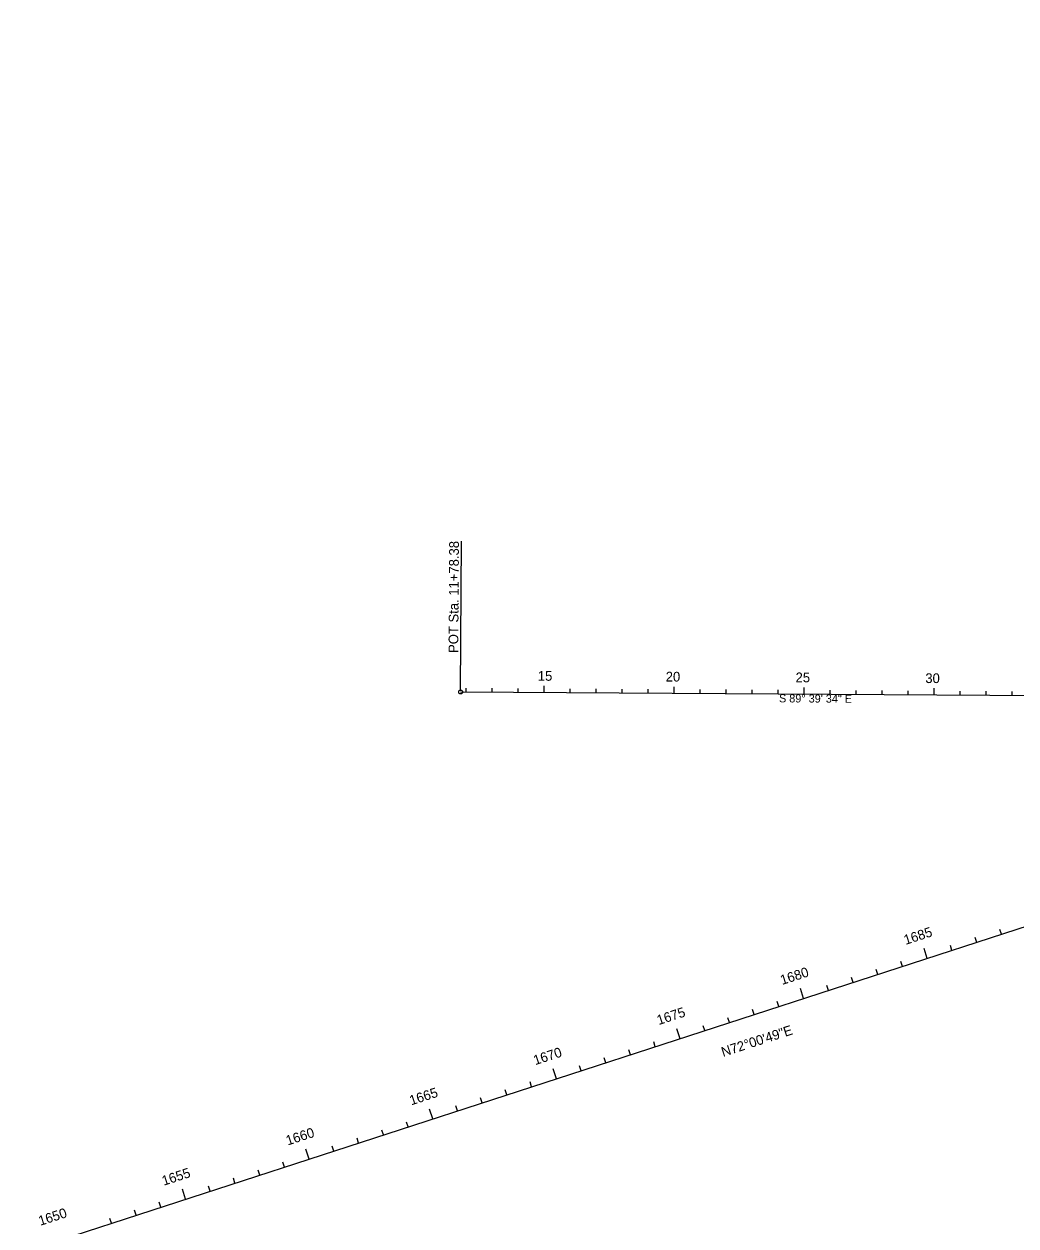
# Model space of a CAD drawing. Extents: x 1280727 to 1452510, y 526233 to 601451.
# Drawn here: x 1420802 to 1424618, y 582241 to 586865 of the extents above; entities that cross this region are included whole.
import ezdxf

# ---------------------------------------------------------------- set-up
doc = ezdxf.new("R2010")
doc.units = 0
for name, color, linetype in [('RW_X_CL', 7, 'Continuous'), ('RW_X_CL_500_Stations', 7, 'Continuous'), ('SH_Text', 7, 'Continuous')]:
    doc.layers.add(name, color=color, linetype=linetype)

msp = doc.modelspace()

# ---------------------------------------------------------------- linework, layer by layer
at = {"layer": 'RW_X_CL'}
for p, q in [((1406994.9, 577659.9), (1435349.1, 586865.3)), ((1422481.4, 584295.6), (1425214.5, 584279.4))]:
    msp.add_line(p, q, dxfattribs=at)
at = {"layer": 'RW_X_CL_500_Stations'}
for p, q in [((1422503, 584295.5), (1422503.1, 584310.5)), ((1422603, 584294.9), (1422603.1, 584309.9)), ((1422703, 584294.3), (1422703.1, 584309.3)), ((1422803, 584293.7), (1422803.1, 584318.7)), ((1422903, 584293.1), (1422903.1, 584308.1)), ((1423003, 584292.5), (1423003.1, 584307.5)), ((1423103, 584291.9), (1423103.1, 584306.9)), ((1423203, 584291.3), (1423203.1, 584306.3)), ((1423303, 584290.7), (1423303.1, 584315.7)), ((1423403, 584290.1), (1423403.1, 584305.1)), ((1423503, 584289.6), (1423503.1, 584304.6)), ((1423603, 584289), (1423603.1, 584304)), ((1423703, 584288.4), (1423703.1, 584303.4)), ((1423803, 584287.8), (1423803.1, 584312.8)), ((1424303, 584284.8), (1424303.1, 584309.8)), ((1423903, 584287.2), (1423903.1, 584302.2)), ((1424003, 584286.6), (1424003.1, 584301.6)), ((1424103, 584286), (1424103.1, 584301)), ((1424203, 584285.4), (1424203.1, 584300.4)), ((1424403, 584284.2), (1424403.1, 584299.2)), ((1424503, 584283.6), (1424503.1, 584298.6)), ((1424603, 584283), (1424603, 584298)), ((1424561.9, 583363.2), (1424555.7, 583382.2)), ((1424466.8, 583332.3), (1424460.6, 583351.3)), ((1424276.5, 583270.5), (1424264.2, 583308.6)), ((1424371.7, 583301.4), (1424365.5, 583320.4)), ((1424181.4, 583239.7), (1424175.2, 583258.7)), ((1423991.2, 583177.9), (1423985, 583196.9)), ((1424086.3, 583208.8), (1424080.1, 583227.8)), ((1423801, 583116.1), (1423788.6, 583154.2)), ((1423896.1, 583147), (1423889.9, 583166)), ((1423705.9, 583085.3), (1423699.7, 583104.3)), ((1423610.7, 583054.4), (1423604.6, 583073.4)), ((1423420.5, 582992.6), (1423414.3, 583011.6)), ((1423515.6, 583023.5), (1423509.5, 583042.5)), ((1423325.4, 582961.7), (1423313.1, 582999.8)), ((1423135.2, 582900), (1423129, 582919)), ((1423230.3, 582930.9), (1423224.1, 582949.9)), ((1423040.1, 582869.1), (1423033.9, 582888.1)), ((1422849.8, 582807.3), (1422837.5, 582845.4)), ((1422945, 582838.2), (1422938.8, 582857.2)), ((1422754.7, 582776.5), (1422748.6, 582795.5)), ((1422564.5, 582714.7), (1422558.3, 582733.7)), ((1422659.6, 582745.6), (1422653.4, 582764.6)), ((1422374.3, 582653), (1422361.9, 582691)), ((1422469.4, 582683.8), (1422463.2, 582702.9)), ((1422279.2, 582622.1), (1422273, 582641.1)), ((1422184.1, 582591.2), (1422177.9, 582610.2)), ((1421993.8, 582529.4), (1421987.6, 582548.5)), ((1422088.9, 582560.3), (1422082.8, 582579.3)), ((1421898.7, 582498.6), (1421886.4, 582536.6)), ((1421708.5, 582436.8), (1421702.3, 582455.8)), ((1421803.6, 582467.7), (1421797.4, 582486.7)), ((1421613.4, 582405.9), (1421607.2, 582424.9)), ((1421423.1, 582344.2), (1421410.8, 582382.2)), ((1421518.3, 582375), (1421512.1, 582394.1)), ((1421328, 582313.3), (1421321.9, 582332.3)), ((1421137.8, 582251.5), (1421131.6, 582270.5)), ((1421232.9, 582282.4), (1421226.7, 582301.4))]:
    msp.add_line(p, q, dxfattribs=at)
at = {"layer": 'SH_Text'}
msp.add_line((1422481.4, 584303.1), (1422484.8, 584876), dxfattribs=at)
msp.add_circle((1422481.4, 584295.6), 7.5, dxfattribs=at)

# ---------------------------------------------------------------- texts
at = {"layer": 'RW_X_CL_500_Stations'}
for s, rotation, p in [('15', 359.6593, (1422778.3, 584338.9)), ('20', 359.6593, (1423270.3, 584335.9)), ('25', 359.6593, (1423769.9, 584333)), ('30', 359.6593, (1424269.1, 584330)), ('1685', 17.9864, (1424193.3, 583322.4)), ('1680', 17.9864, (1423718.1, 583168.1)), ('1675', 17.9864, (1423243.4, 583014)), ('1670', 17.9864, (1422768.3, 582859.7)), ('1665', 17.9864, (1422291.4, 582704.9)), ('1660', 17.9864, (1421816.3, 582550.7)), ('1655', 17.9864, (1421339.3, 582395.8)), ('1650', 17.9864, (1420864.2, 582241.5))]:
    msp.add_text(s, height=37.5, rotation=rotation, dxfattribs=at).set_placement(p)
at = {"layer": 'SH_Text'}
for s, height, rotation, p in [('POT Sta. 11+78.38', 37.5, 89.6593, (1422472.3, 584445.7)), ('S 89° 39\' 34" E', 31.2, 359.6593, (1423706.2, 584255.6)), ('N72°00\'49"E', 37.5, 17.9864, (1423491.3, 582891.3))]:
    msp.add_text(s, height=height, rotation=rotation, dxfattribs=at).set_placement(p)

doc.saveas('drawing.dxf')
